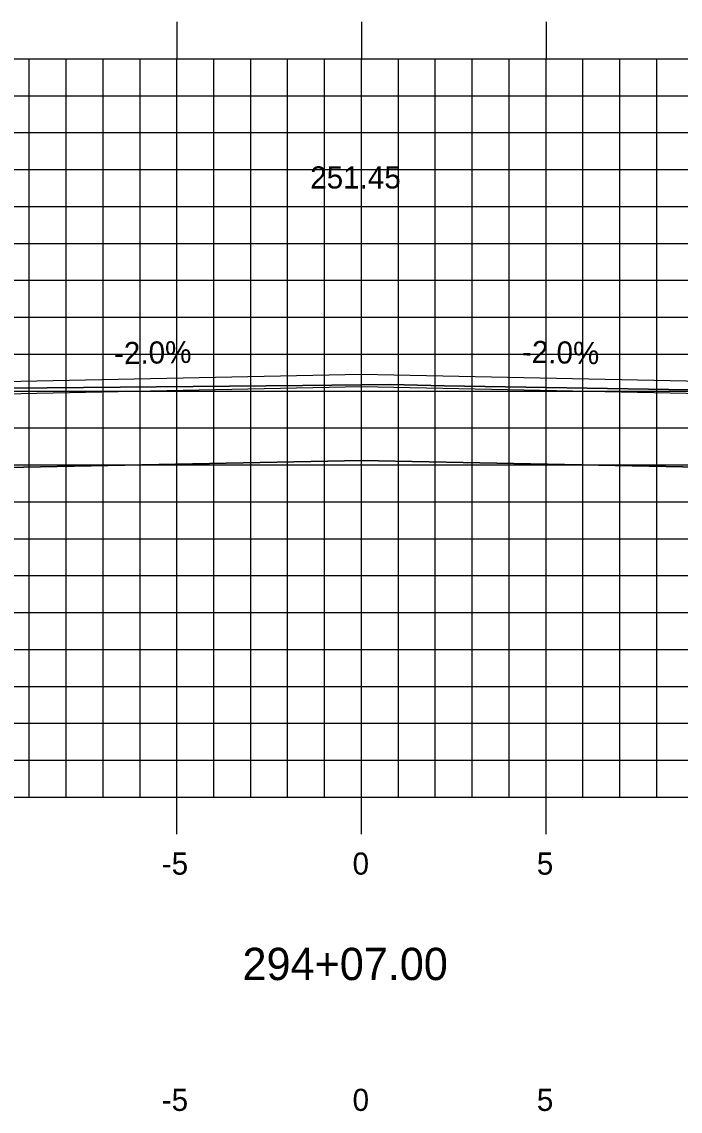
# Model space of a CAD drawing. Extents: x 859129 to 859299, y 366268 to 366378.
# Drawn here: x 859203.26 to 859221.1, y 366328.73 to 366358.24 of the extents above; entities that cross this region are included whole.
import ezdxf

# ---------------------------------------------------------------- set-up
doc = ezdxf.new("R2010")
doc.units = 0
for name, color, linetype in [('ANNOTATION', 7, 'Continuous'), ('D_Roadway_Centerline_Text', 7, 'Continuous'), ('D_Roadway_Edge_Shoulder', 7, 'Continuous'), ('D_Roadway_SubGrade', 7, 'Continuous'), ('H_V ANNOTATION', 7, 'Continuous'), ('JUNK COM EXC', 7, 'Continuous'), ('MAJOR', 7, 'Continuous'), ('MINOR', 7, 'Continuous'), ('S_Roadway_Centerline', 7, 'Continuous')]:
    doc.layers.add(name, color=color, linetype=linetype)

msp = doc.modelspace()

# ---------------------------------------------------------------- linework, layer by layer
at = {"layer": 'D_Roadway_Edge_Shoulder'}
msp.add_lwpolyline([(859197.466, 366348.311), (859201.462, 366348.47), (859212.462, 366348.69), (859223.462, 366348.47), (859227.464, 366348.311)], dxfattribs=at)
at = {"layer": 'D_Roadway_SubGrade'}
msp.add_lwpolyline([(859201.462, 366346.137), (859201.462, 366348.137), (859212.462, 366348.357), (859223.462, 366348.137), (859223.462, 366346.137), (859212.462, 366346.357)], close=True, dxfattribs=at)
at = {"layer": 'JUNK COM EXC'}
msp.add_lwpolyline([(859196.462, 366348.151), (859196.462, 366346.037), (859201.462, 366346.137), (859212.462, 366346.357), (859223.462, 366346.137), (859228.464, 366346.037), (859228.466, 366348.614), (859227.539, 366348.481), (859226.052, 366348.278), (859225.954, 366348.264), (859225.274, 366348.251), (859225.106, 366348.22), (859222.892, 366348.262), (859222.456, 366348.252), (859214.703, 366348.376), (859213.255, 366348.415), (859210.867, 366348.383), (859201.956, 366348.308), (859200.211, 366348.266), (859197.405, 366348.194), (859196.462, 366348.151)], dxfattribs=at)
at = {"layer": 'MAJOR'}
for p, q in [((859207.462, 366358.238), (859207.462, 366357.236)), ((859212.462, 366358.238), (859212.462, 366357.236)), ((859217.462, 366358.238), (859217.462, 366357.236)), ((859142.462, 366357.236), (859282.462, 366357.236)), ((859142.462, 366357.236), (859282.462, 366357.236)), ((859207.462, 366337.236), (859207.462, 366357.236)), ((859212.462, 366337.236), (859212.462, 366357.236)), ((859217.462, 366337.236), (859217.462, 366357.236)), ((859142.462, 366352.236), (859282.462, 366352.236)), ((859142.462, 366347.236), (859282.462, 366347.236)), ((859142.462, 366342.236), (859282.462, 366342.236)), ((859142.462, 366337.236), (859282.462, 366337.236)), ((859142.462, 366337.236), (859282.462, 366337.236)), ((859207.462, 366336.234), (859207.462, 366337.236)), ((859212.462, 366336.234), (859212.462, 366337.236)), ((859217.462, 366336.234), (859217.462, 366337.236))]:
    msp.add_line(p, q, dxfattribs=at)
at = {"layer": 'MINOR'}
for p, q in [((859203.462, 366337.236), (859203.462, 366357.236)), ((859204.462, 366337.236), (859204.462, 366357.236)), ((859205.462, 366337.236), (859205.462, 366357.236)), ((859206.462, 366337.236), (859206.462, 366357.236)), ((859208.462, 366337.236), (859208.462, 366357.236)), ((859209.462, 366337.236), (859209.462, 366357.236)), ((859210.462, 366337.236), (859210.462, 366357.236)), ((859211.462, 366337.236), (859211.462, 366357.236)), ((859213.462, 366337.236), (859213.462, 366357.236)), ((859214.462, 366337.236), (859214.462, 366357.236)), ((859215.462, 366337.236), (859215.462, 366357.236)), ((859216.462, 366337.236), (859216.462, 366357.236)), ((859218.462, 366337.236), (859218.462, 366357.236)), ((859219.462, 366337.236), (859219.462, 366357.236)), ((859220.462, 366337.236), (859220.462, 366357.236)), ((859142.462, 366356.236), (859282.462, 366356.236)), ((859142.462, 366355.236), (859282.462, 366355.236)), ((859142.462, 366354.236), (859282.462, 366354.236)), ((859142.462, 366353.236), (859282.462, 366353.236)), ((859142.462, 366351.236), (859282.462, 366351.236)), ((859142.462, 366350.236), (859282.462, 366350.236)), ((859142.462, 366349.236), (859282.462, 366349.236)), ((859142.462, 366348.236), (859282.462, 366348.236)), ((859142.462, 366346.236), (859282.462, 366346.236)), ((859142.462, 366345.236), (859282.462, 366345.236)), ((859142.462, 366344.236), (859282.462, 366344.236)), ((859142.462, 366343.236), (859282.462, 366343.236)), ((859142.462, 366341.236), (859282.462, 366341.236)), ((859142.462, 366340.236), (859282.462, 366340.236)), ((859142.462, 366339.236), (859282.462, 366339.236)), ((859142.462, 366338.236), (859282.462, 366338.236))]:
    msp.add_line(p, q, dxfattribs=at)
at = {"layer": 'S_Roadway_Centerline'}
msp.add_lwpolyline([(859169.353, 366346.993), (859173.61, 366346.883), (859175.658, 366347.011), (859183.025, 366347.23), (859192.828, 366347.969), (859193.405, 366348.01), (859197.405, 366348.194), (859200.211, 366348.266), (859201.956, 366348.308), (859210.867, 366348.383), (859213.255, 366348.415), (859214.703, 366348.376), (859222.456, 366348.252), (859222.892, 366348.262), (859225.106, 366348.22), (859225.274, 366348.251), (859225.954, 366348.264), (859226.052, 366348.278), (859227.539, 366348.481), (859228.478, 366348.616), (859228.625, 366348.643), (859229.051, 366348.623), (859249.622, 366347.669)], dxfattribs=at)

# ---------------------------------------------------------------- texts
at = {"layer": 'ANNOTATION'}
for rotation, p in [(1.1458, (859205.765, 366348.957)), (358.8542, (859216.805, 366349.004))]:
    msp.add_text('-2.0%', height=0.6, rotation=rotation, dxfattribs=at).set_placement(p)
at = {"layer": 'D_Roadway_Centerline_Text'}
msp.add_text('251.45', height=0.6, dxfattribs=at).set_placement((859211.073, 366353.722))
at = {"layer": 'H_V ANNOTATION'}
for s, height, p in [('-5', 0.6, (859207.052, 366335.136)), ('0', 0.6, (859212.221, 366335.136)), ('5', 0.6, (859217.213, 366335.136)), ('294+07.00', 0.875, (859209.239, 366332.28)), ('-5', 0.6, (859207.052, 366328.736)), ('0', 0.6, (859212.221, 366328.736)), ('5', 0.6, (859217.213, 366328.736))]:
    msp.add_text(s, height=height, dxfattribs=at).set_placement(p)
at = {"layer": 'S_Roadway_Centerline'}
for s, p in [('C', (859213.249, 366348.415)), ('L', (859213.255, 366348.407))]:
    msp.add_text(s, height=0.0146, dxfattribs=at).set_placement(p)

doc.saveas('drawing.dxf')
